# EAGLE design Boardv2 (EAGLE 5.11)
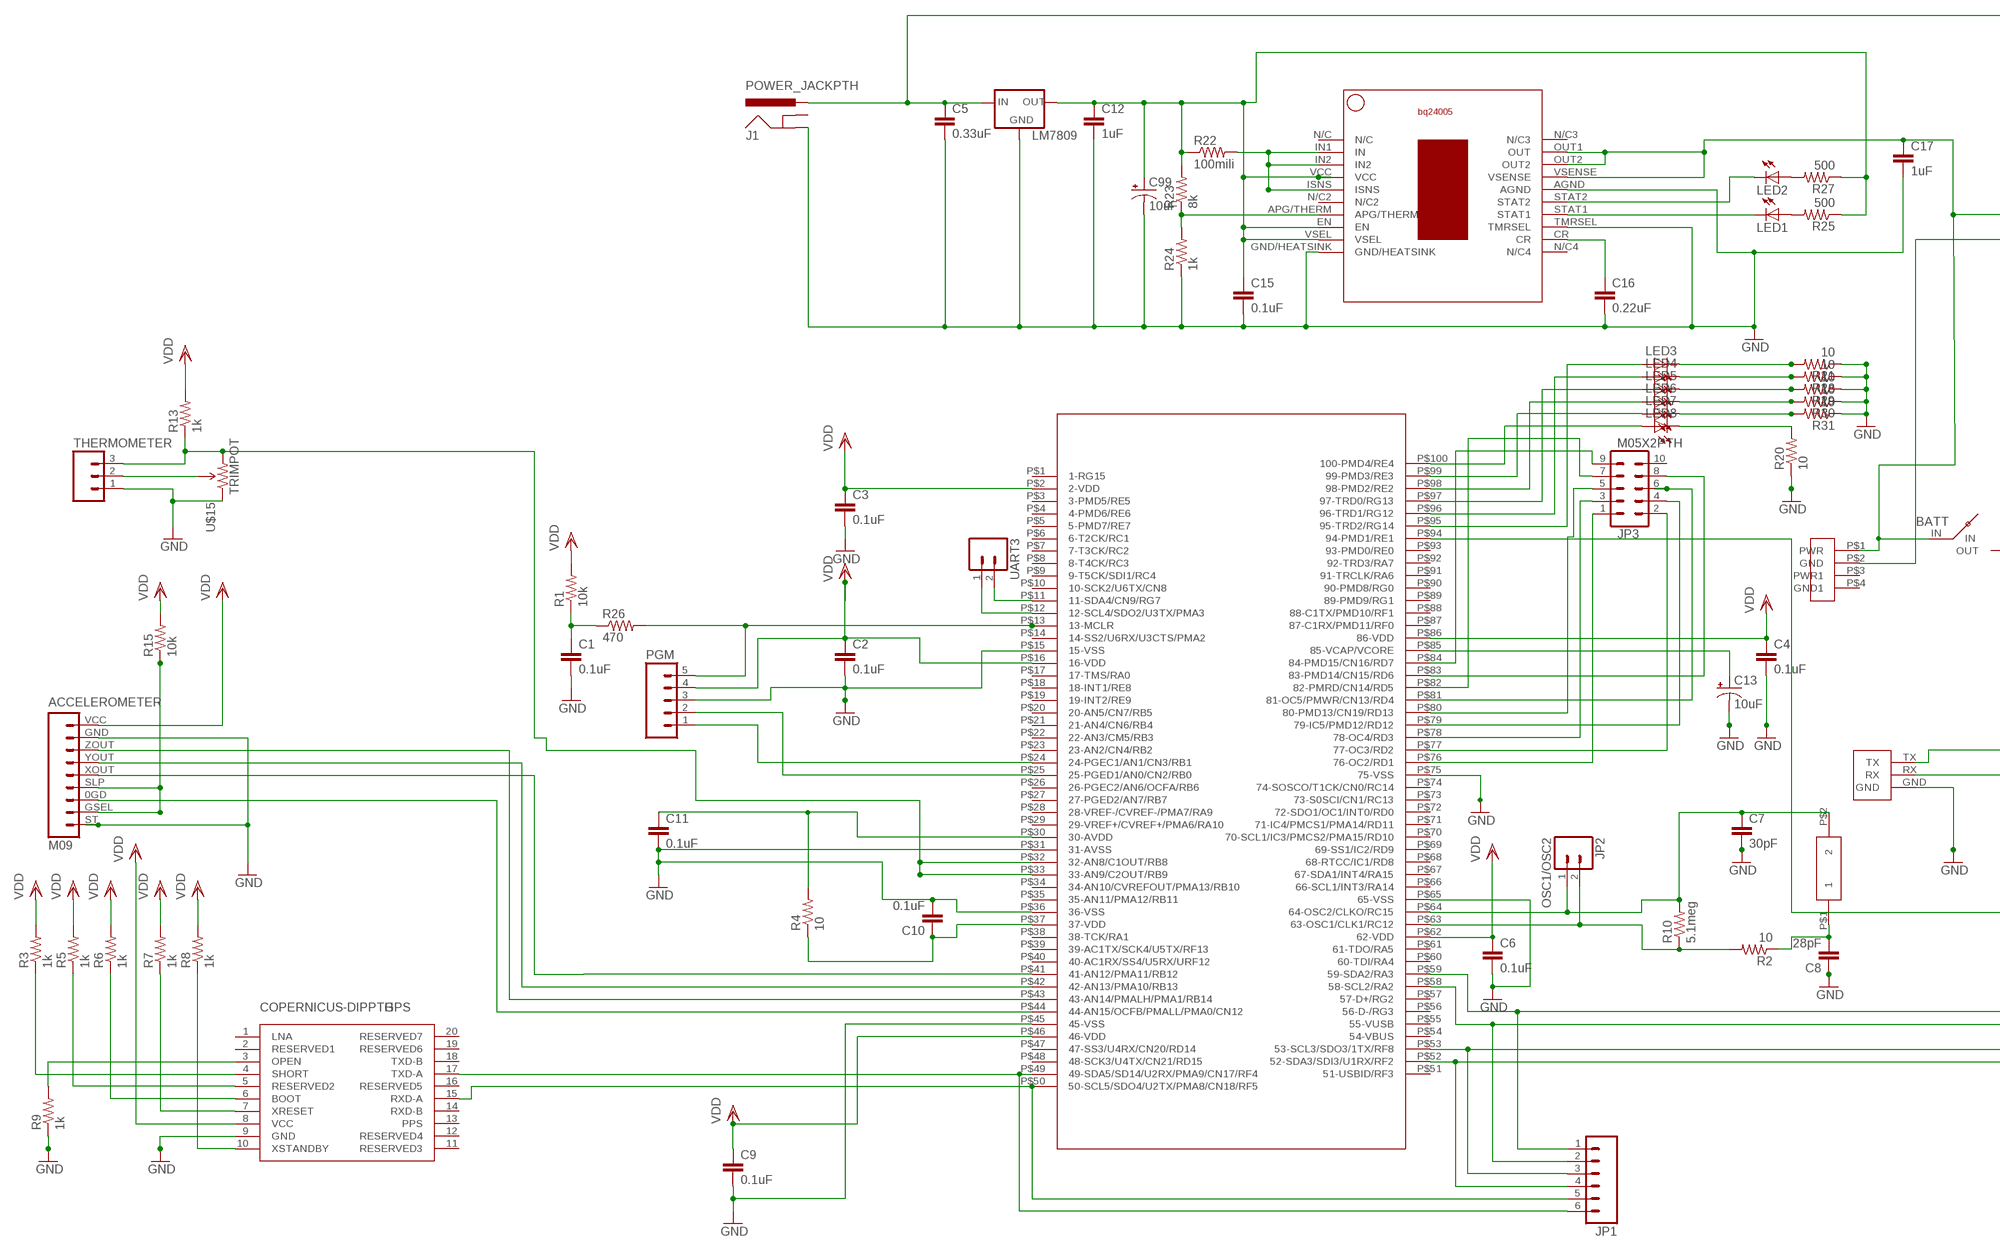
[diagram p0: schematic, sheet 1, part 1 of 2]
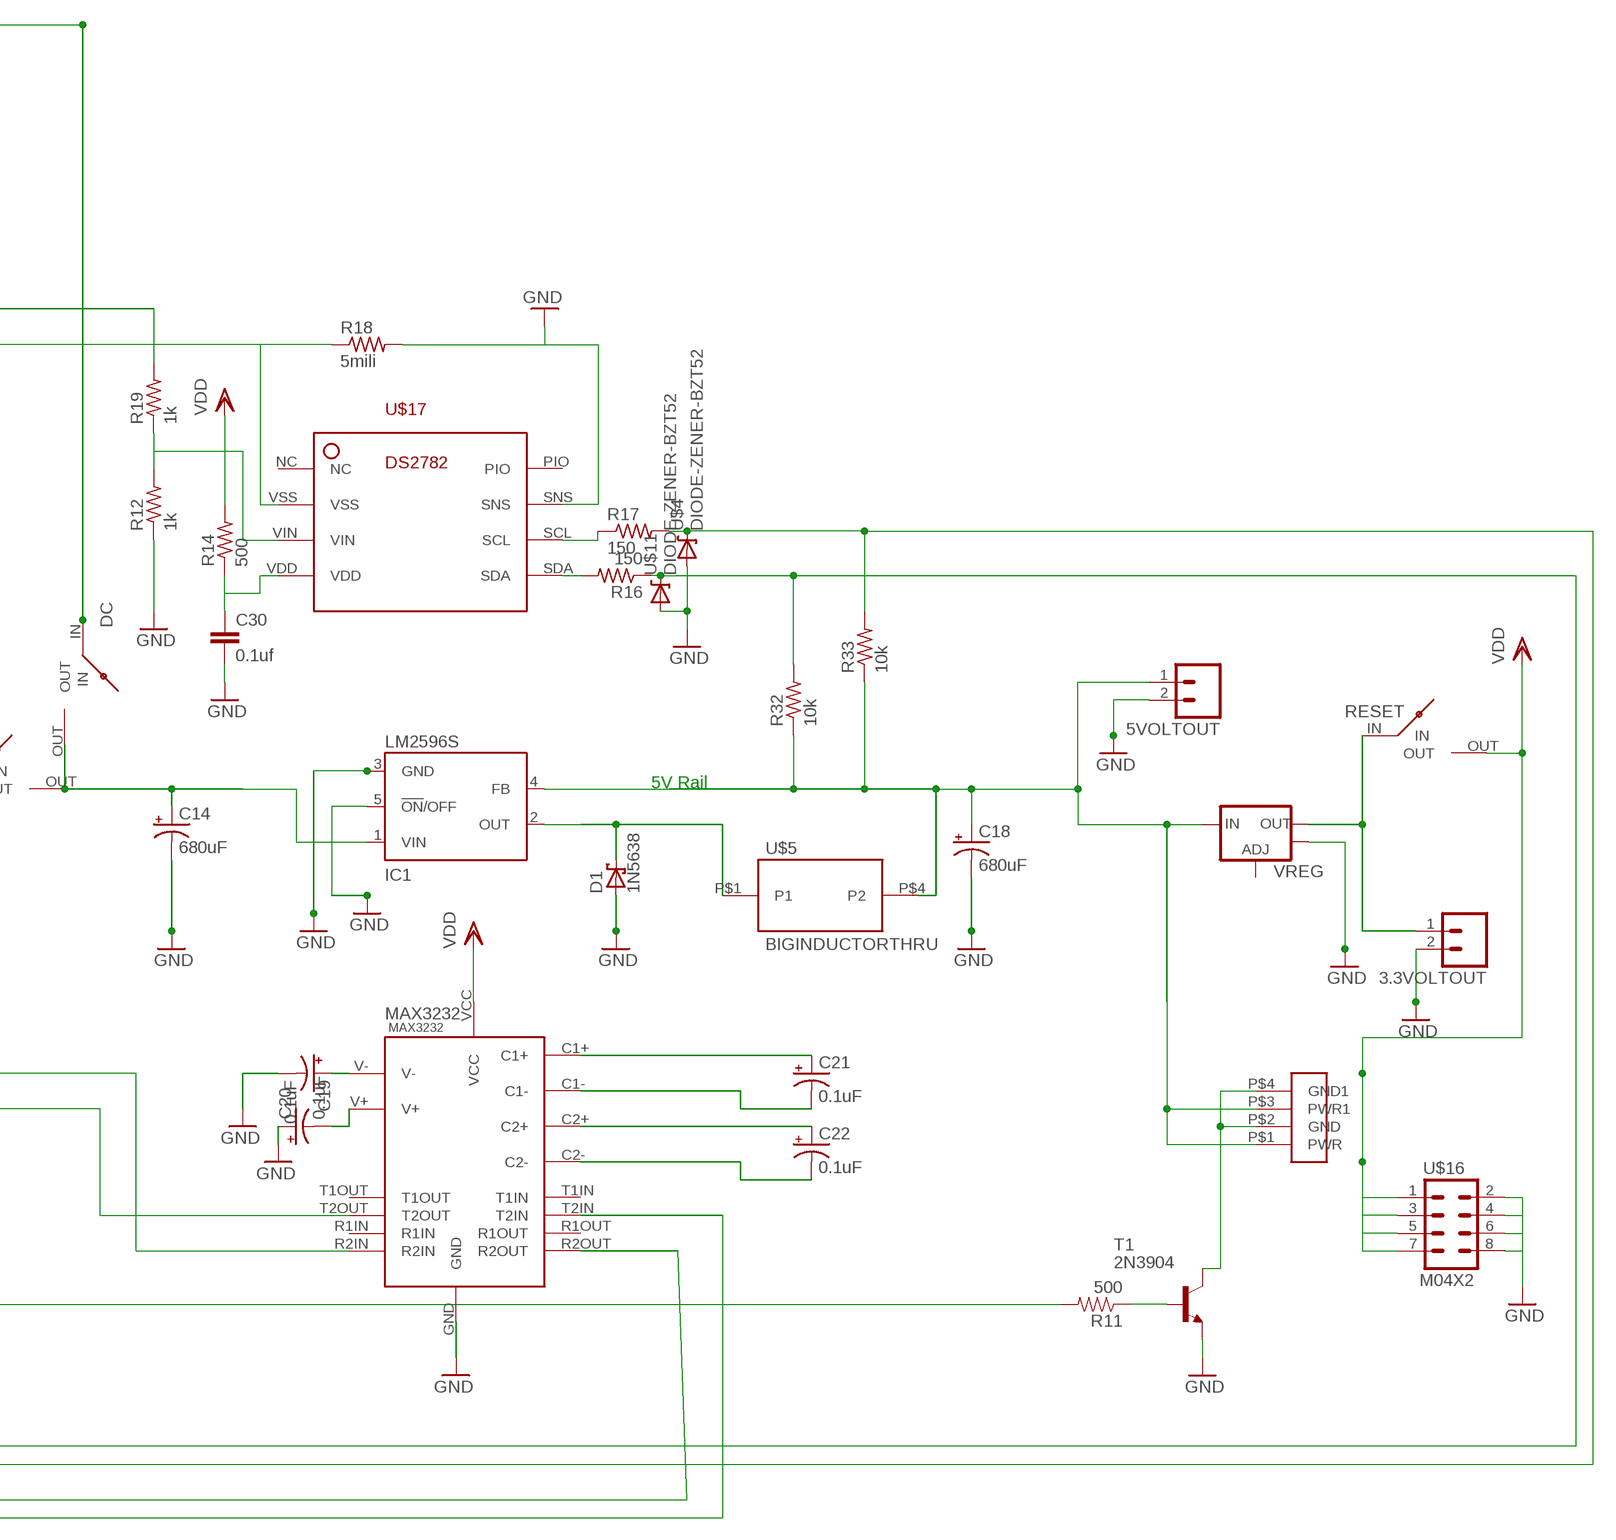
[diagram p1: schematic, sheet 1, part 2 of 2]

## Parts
3.3VOLTOUT  M02LOCK  [1X02_LOCK]
5VOLTOUT  M02PTH  [1X02]
ACCELEROMETER  M09  [1X09]
BATT  HUD_LOAD_SWITCH  [1X02@1]
C1  0.1uF  CAP1206  [1206]
C2  0.1uF  CAP1206  [1206]
C3  0.1uF  CAP1206  [1206]
C4  0.1uF  CAP1206  [1206]
C5  0.33uF  CAP1206  [1206]
C6  0.1uF  CAP1206  [1206]
C7  30pF  CAP1206  [1206]
C8  28pF  CAP1206  [1206]
C9  0.1uF  CAP1206  [1206]
C10  0.1uF  CAP1206  [1206]
C11  0.1uF  CAP1206  [1206]
C12  1uF  CAP1206  [1206]
C13  10uF  CAP_POL1206-KIT  [EIA3216-KIT]
C14  680uF  CAP_POLG  [PANASONIC_G]
C15  0.1uF  CAP1206  [1206]
C16  0.22uF  CAP1206  [1206]
C17  1uF  CAP1206  [1206]
C18  680uF  CAP_POLG  [PANASONIC_G]
C19  0.1uF  CAP_POL  [HUD_4MM_CAP_POL]
C20  0.1uF  CAP_POL  [HUD_4MM_CAP_POL]
C21  0.1uF  CAP_POL  [HUD_4MM_CAP_POL]
C22  0.1uF  CAP_POL  [HUD_4MM_CAP_POL]
C30  0.1uf  CAP1206  [1206]
C99  10uF  CAP_POLC  [PANASONIC_C]
D1  1N5638  SCHOTTKY-DIODESMC  [SMC]
DC  HUD_LOAD_SWITCH  [1X02@1]
GPS  COPERNICUS-DIPPTH  [COPERNICUS-DIP]
IC1  LM2596S  [TO263-5]
J1  POWER_JACKPTH  [POWER_JACK_PTH]
JP1  M06SIP  [1X06]
JP2  OSC1/OSC2  M02NG  [1X02]
JP3  M05X2PTH  [AVR_ICSP]
LED1  LED1206  [LED-1206]
LED2  LED1206  [LED-1206]
LED3  LED1206  [LED-1206]
LED4  LED1206  [LED-1206]
LED5  LED1206  [LED-1206]
LED6  LED1206  [LED-1206]
LED7  LED1206  [LED-1206]
LED8  LED1206  [LED-1206]
LM7809  V_REG_78XX-TO-220  [TO-220-ALT]
MAX3232  MAX3232TSOP-16  [MAX3232]
OSC  OSCILLATOR  [OSCILLATOR]
PGM  M05LOCK  [1X05_LOCK]
R1  10k  R-US_M1206  [M1206]
R2  10  R-US_M1206  [M1206]
R3  1k  R-US_M1206  [M1206]
R4  10  R-US_M1206  [M1206]
R5  1k  R-US_M1206  [M1206]
R6  1k  R-US_M1206  [M1206]
R7  1k  R-US_M1206  [M1206]
R8  1k  R-US_M1206  [M1206]
R9  1k  R-US_M1206  [M1206]
R10  5.1meg  R-US_M1206  [M1206]
R11  500  RESISTOR1206  [1206]
R12  1k  R-US_M1206  [M1206]
R13  1k  R-US_M1206  [M1206]
R14  500  R-US_M1206  [M1206]
R15  10k  R-US_M1206  [M1206]
R16  150  R-US_M1206  [M1206]
R17  150  R-US_M1206  [M1206]
R18  5mili  R-US_M1206  [M1206]
R19  1k  R-US_M1206  [M1206]
R20  10  RESISTOR1206  [1206]
R21  10  RESISTOR1206  [1206]
R22  100mili  RESISTOR1206  [1206]
R23  8k  RESISTOR1206  [1206]
R24  1k  RESISTOR1206  [1206]
R25  500  RESISTOR1206  [1206]
R26  470  R-US_M1206  [M1206]
R27  500  RESISTOR1206  [1206]
R28  10  RESISTOR1206  [1206]
R29  10  RESISTOR1206  [1206]
R30  10  RESISTOR1206  [1206]
R31  10  RESISTOR1206  [1206]
R32  10k  R-US_M1206  [M1206]
R33  10k  R-US_M1206  [M1206]
RESET  HUD_LOAD_SWITCH  [1X02@1]
T1  2N3904  [TO92]
THERMOMETER  M03LOCK  [1X03_LOCK]
U$1  PIC32MX564F128L  [PIC32]
U$2  BQ24005TSSOP-20VAR  [BQ24005]
U$4  DIODE-ZENER-BZT52  [SOD-323]
U$5  BIGINDUCTORTHRU  [BIGINDUCTOR]
U$6  4PINCON  [4PINCON]
U$7  4PINCON  [4PINCON]
U$9  UART_HEADERTHRU  [UART_HEADER]
U$11  DIODE-ZENER-BZT52  [SOD-323]
U$15  TRIMPOT  [TRIMPOT]
U$16  M04X2  [2X4]
U$17  DS2782TSSOP-8  [DS2782]
UART3  M02PTH  [1X02]
VREG  V_REG_LM1117SOT223  [SOT223]

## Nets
GND: 3.3VOLTOUT.2 5VOLTOUT.2 ACCELEROMETER.GND ACCELEROMETER.ST C1.2 C2.2 C3.2 C4.2 C5.2 C6.2 C7.2 C8.1 C9.2 C10.2 C11.2 C12.2 C13.C(-) C14.- C15.2 C16.2 C17.2 C18.- C19.MINUS(-) C20.PLUS(+) C30.2 C99.- D1.A GPS.9(GND) IC1.3(GND) IC1.5(!ON!/OFF) J1.GND LM7809.GND MAX3232.GND PGM.3 R9.1 R12.1 R18.2 R20.1 R21.1 R24.1 R28.1 R29.1 R30.1 R31.1 T1.3(E) THERMOMETER.1 U$1.P$15(15-VSS) U$1.P$31(31-AVSS) U$1.P$36(36-VSS) U$1.P$45(45-VSS) U$1.P$65(65-VSS) U$1.P$75(75-VSS) U$2.AGND U$2.GND/HEATSINK U$2.TMRSEL U$4.2(A) U$9.GND U$11.2(A) U$15.P$1(CCW) U$16.2 U$16.4 U$16.6 U$16.8 U$17.SNS VREG.4(OUT)
N$1: C1.1 R1.1 R26.1
N$2: C7.1 JP2.1 OSC.P$2 R10.2 U$1.P$64(64-OSC2/CLKO/RC15)
N$3: R13.1 THERMOMETER.3 U$1.P$32(32-AN8/C1OUT/RB8) U$1.P$33(33-AN9/C2OUT/RB9) U$15.P$3(CW)
N$4: PGM.1 U$1.P$24(24-PGEC1/AN1/CN3/RB1)
N$5: PGM.2 U$1.P$25(25-PGED1/AN0/CN2/RB0)
N$6: BATT.OUT C14.+ DC.OUT IC1.1(VIN)
N$7: C8.2 OSC.P$1 R2.1
N$8: GPS.15(RXD-A) JP1.5 U$1.P$50(50-SCL5/SDO4/U2TX/PMA8/CN18/RF5)
N$9: LED7.C R31.2
N$10: C30.1 R14.1 U$17.VDD
N$11: ACCELEROMETER.GSEL ACCELEROMETER.SLP R15.1
N$12: R18.1 U$6.P$2(GND) U$17.VSS
N$13: GPS.3(OPEN) R9.2
N$14: JP3.9 U$1.P$84(84-PMD15/CN16/RD7)
N$15: LED8.A U$1.P$100(100-PMD4/RE4)
N$16: GPS.10(XSTANDBY) R8.1
N$17: GPS.7(XRESET) R7.1
N$18: GPS.6(BOOT) R6.1
N$19: GPS.5(RESERVED2) R5.1
N$20: C5.1 DC.IN J1.PWR LM7809.IN
N$21: LED7.A U$1.P$99(99-PMD3/RE3)
N$22: LED6.A U$1.P$98(98-PMD2/RE2)
N$23: LED5.A U$1.P$97(97-TRD0/RG13)
N$24: LED4.A U$1.P$96(96-TRD1/RG12)
N$25: R22.2 U$2.IN1(IN) U$2.IN2 U$2.ISNS
N$26: R23.1 R24.2 U$2.APG/THERM
N$27: ACCELEROMETER.0GD U$1.P$44(44-AN15/OCFB/PMALL/PMA0/CN12)
N$28: BATT.IN C17.1 R19.2 U$2.OUT1(OUT) U$2.OUT2 U$2.VSENSE U$6.P$1(PWR)
N$29: LED3.A U$1.P$95(95-TRD2/RG14)
N$30: C16.1 U$2.CR
N$31: LED2.A R27.2
N$32: LED1.A R25.2
N$33: JP3.1 U$1.P$76(76-OC2/RD1)
N$34: LED1.C U$2.STAT1
N$35: LED2.C U$2.STAT2
N$36: 5VOLTOUT.1 C18.+ IC1.4(FB) R32.1 R33.1 U$5.P$4(P2) U$7.P$1(PWR) U$7.P$3(PWR1) VREG.3(IN)
N$37: U$1.P$11(11-SDA4/CN9/RG7) UART3.2
N$38: C12.1 C15.1 C99.+ LM7809.OUT R22.1 R23.2 R25.1 R27.1 U$2.EN U$2.VCC U$2.VSEL
N$39: JP3.2 U$1.P$77(77-OC3/RD2)
N$40: JP3.3 U$1.P$78(78-OC4/RD3)
N$41: JP3.4 U$1.P$79(79-IC5/PMD12/RD12)
N$42: THERMOMETER.2 U$15.P$2(WIPER)
N$43: JP3.6 U$1.P$81(81-OC5/PMWR/CN13/RD4)
N$44: JP3.8 U$1.P$83(83-PMD14/CN15/RD6)
N$45: ACCELEROMETER.XOUT U$1.P$41(41-AN12/PMA11/RB12)
N$46: ACCELEROMETER.YOUT U$1.P$42(42-AN13/PMA10/RB13)
N$47: ACCELEROMETER.ZOUT U$1.P$43(43-AN14/PMALH/PMA1/RB14)
N$48: C10.1 R4.1 U$1.P$37(37-VDD)
N$49: JP3.5 U$1.P$80(80-PMD13/CN19/RD13)
N$50: JP3.7 U$1.P$82(82-PMRD/CN14/RD5)
N$51: C11.1 R4.2 U$1.P$30(30-AVDD)
N$52: U$1.P$12(12-SCL4/SDO2/U3TX/PMA3) UART3.1
N$53: LED3.C R21.2
N$54: LED4.C R28.2
N$55: LED5.C R29.2
N$56: LED6.C R30.2
N$57: JP2.2 R2.2 R10.1 U$1.P$63(63-OSC1/CLK1/RC12)
N$58: LED8.C R20.2
N$59: R11.2 U$1.P$94(94-PMD1/RE1)
N$60: PGM.5 R26.2 U$1.P$13(13-MCLR)
N$61: JP1.2 R17.2 R33.2 U$1.P$58(58-SCL2/RA2) U$4.1(C)
N$62: R17.1 U$17.SCL
N$63: MAX3232.T2OUT U$9.RX
N$64: R12.2 R19.1 U$17.VIN
N$65: R11.1 T1.2(B)
N$66: T1.1(C) U$7.P$2(GND) U$7.P$4(GND1)
N$67: GPS.4(SHORT) R3.1
N$68: 3.3VOLTOUT.1 RESET.IN VREG.2(OUT)
N$69: JP1.3 MAX3232.R2OUT U$1.P$53(53-SCL3/SDO3/1TX/RF8)
N$70: R16.2 U$17.SDA
N$73: C13.A(+) U$1.P$85(85-VCAP/VCORE)
N$92: GPS.17(TXD-A) JP1.6 U$1.P$49(49-SDA5/SD14/U2RX/PMA9/CN17/RF4)
N$96: D1.C IC1.2(OUT) U$5.P$1(P1)
N$97: JP1.1 R16.1 R32.2 U$1.P$59(59-SDA2/RA3) U$11.1(C)
N$116: JP1.4 MAX3232.T2IN U$1.P$52(52-SDA3/SDI3/U1RX/RF2)
N$117: C21.PLUS(+) MAX3232.C1+
N$118: C21.MINUS(-) MAX3232.C1-
N$119: C22.PLUS(+) MAX3232.C2+
N$120: C22.MINUS(-) MAX3232.C2-
N$121: C19.PLUS(+) MAX3232.V-
N$122: C20.MINUS(-) MAX3232.V+
N$123: MAX3232.R2IN U$9.TX
VDD: ACCELEROMETER.VCC C2.1 C3.1 C4.1 C6.1 C9.1 GPS.8(VCC) MAX3232.VCC PGM.4 R1.2 R3.2 R5.2 R6.2 R7.2 R8.2 R13.2 R14.2 R15.2 RESET.OUT U$1.P$2(2-VDD) U$1.P$16(16-VDD) U$1.P$46(46-VDD) U$1.P$62(62-VDD) U$1.P$86(86-VDD) U$16.1 U$16.3 U$16.5 U$16.7
Unconnected: GPS.1(LNA) GPS.2(RESERVED1) GPS.11(RESERVED3) GPS.12(RESERVED4) GPS.13(PPS) GPS.14(RXD-B) GPS.16(RESERVED5) GPS.18(TXD-B) GPS.19(RESERVED6) GPS.20(RESERVED7) J1.GNDBREAK JP3.10 MAX3232.R1IN MAX3232.R1OUT MAX3232.T1IN MAX3232.T1OUT U$1.P$1(1-RG15) U$1.P$3(3-PMD5/RE5) U$1.P$4(4-PMD6/RE6) U$1.P$5(5-PMD7/RE7) U$1.P$6(6-T2CK/RC1) U$1.P$7(7-T3CK/RC2) U$1.P$8(8-T4CK/RC3) U$1.P$9(9-T5CK/SDI1/RC4) U$1.P$10(10-SCK2/U6TX/CN8) U$1.P$14(14-SS2/U6RX/U3CTS/PMA2) U$1.P$17(17-TMS/RA0) U$1.P$18(18-INT1/RE8) U$1.P$19(19-INT2/RE9) U$1.P$20(20-AN5/CN7/RB5) U$1.P$21(21-AN4/CN6/RB4) U$1.P$22(22-AN3/CM5/RB3) U$1.P$23(23-AN2/CN4/RB2) U$1.P$26(26-PGEC2/AN6/OCFA/RB6) U$1.P$27(27-PGED2/AN7/RB7) U$1.P$28(28-VREF-/CVREF-/PMA7/RA9) U$1.P$29(29-VREF+/CVREF+/PMA6/RA10) U$1.P$34(34-AN10/CVREFOUT/PMA13/RB10) U$1.P$35(35-AN11/PMA12/RB11) U$1.P$38(38-TCK/RA1) U$1.P$39(39-AC1TX/SCK4/U5TX/RF13) U$1.P$40(40-AC1RX/SS4/U5RX/URF12) U$1.P$47(47-SS3/U4RX/CN20/RD14) U$1.P$48(48-SCK3/U4TX/CN21/RD15) U$1.P$51(51-USBID/RF3) U$1.P$54(54-VBUS) U$1.P$55(55-VUSB) U$1.P$56(56-D-/RG3) U$1.P$57(57-D+/RG2) U$1.P$60(60-TDI/RA4) U$1.P$61(61-TDO/RA5) U$1.P$66(66-SCL1/INT3/RA14) U$1.P$67(67-SDA1/INT4/RA15) U$1.P$68(68-RTCC/IC1/RD8) U$1.P$69(69-SS1/IC2/RD9) U$1.P$70(70-SCL1/IC3/PMCS2/PMA15/RD10) U$1.P$71(71-IC4/PMCS1/PMA14/RD11) U$1.P$72(72-SDO1/OC1/INT0/RD0) U$1.P$73(73-S0SCI/CN1/RC13) U$1.P$74(74-SOSCO/T1CK/CN0/RC14) U$1.P$87(87-C1RX/PMD11/RF0) U$1.P$88(88-C1TX/PMD10/RF1) U$1.P$89(89-PMD9/RG1) U$1.P$90(90-PMD8/RG0) U$1.P$91(91-TRCLK/RA6) U$1.P$92(92-TRD3/RA7) U$1.P$93(93-PMD0/RE0) U$2.N/C U$2.N/C2 U$2.N/C3 U$2.N/C4 U$6.P$3(PWR1) U$6.P$4(GND1) U$17.NC U$17.PIO VREG.1(ADJ)

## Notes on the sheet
- 5V Rail

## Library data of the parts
3.3VOLTOUT 5VOLTOUT UART3 = SparkFun:M02: Header 2
ACCELEROMETER = SparkFun:M09: Header 9 Standard 9-pin 0.1" header. Use with straight break away headers (SKU : PRT-00116), right angle break away headers (PRT-00553), swiss pins (PRT-00743), machine pins (PRT-00117), and female headers (PRT-00115).
BATT DC RESET = SparkFun:HUD_LOAD_SWITCH
C1-C12 C15-C17 C30 = SparkFun:CAP: Capacitor
C13 C14 C18-C22 C99 = SparkFun:CAP_POL: Capacitor Polarized
D1 = diode:SCHOTTKY-DIODE: Schottky Diode
GPS = SparkFun:COPERNICUS-DIP
IC1 = national-semiconductor:LM2596: SIMPLE SWITCHER® Power Converter 150 kHz 3A Step-Down Voltage Regulator Source: http://www.national.com/ds/LM/LM2596.pdf; MF: NATIONAL SEMICONDUCTOR; MPN: LM2596S-ADJ/NOPB; OC_FARNELL: 9494367; OC_NEWARK: 41K3842
J1 = SparkFun:POWER_JACK: Power Jack This is the standard 5.5mm barrel jack for power. The PTH is the most common, proven, reliable, footprint. All others are experimental. The Slot footprint only works if the mill layer is transmitted to the PCB fab house so be warned. Spark Fun Electronics SKU : PRT-00119. Mating wall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
JP1 = SparkFun:M06: Header 6 Standard 6-pin 0.1" header. Use with straight break away headers (SKU : PRT-00116), right angle break away headers (PRT-00553), swiss pins (PRT-00743), machine pins (PRT-00117), and female headers (PRT-00115). Molex polarized connector foot print use with SKU : PRT-08094 with associated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
JP2 = SparkFun:M02NG
JP3 = SparkFun:M05X2: Header 5x2 Standard 10-pin dual row 0.1" header. Commonly used with AVR-ISP. Use with Spark Fun Electronics SKU: PRT-00778
LED1-LED8 = SparkFun:LED: LEDs
LM7809 = SparkFun:V_REG_78XX: Voltage Regulator Standard 7805 5V regulator. IGO (Input Ground Output). Spark Fun Electronics SKU : COM-00107
MAX3232 = SMD Mods:MAX3232
OSC = IncredibleHud:OSCILLATOR
PGM = SparkFun:M05: Header 5 Standard 5-pin 0.1" header. Use with straight break away headers (SKU : PRT-00116), right angle break away headers (PRT-00553), swiss pins (PRT-00743), machine pins (PRT-00117), and female headers (PRT-00115). Molex polarized connector foot print use with SKU : PRT-08230 with associated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
R1-R10 R12-R19 R26 R32 R33 = resistor:R-US_: RESISTOR, American symbol
R11 R20-R25 R27-R31 = SparkFun:RESISTOR: Resistor
T1 = transistor:2N3904: NPN TRANSISTOR
THERMOMETER = SparkFun:M03: Header 3 Standard 3-pin 0.1" header. Use with straight break away headers (SKU : PRT-00116), right angle break away headers (PRT-00553), swiss pins (PRT-00743), machine pins (PRT-00117), and female headers (PRT-00115). Molex polarized connector foot print use with SKU : PRT-08232 with associated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
U$1 = IncredibleHud:PIC32MX564F128L
U$2 = SMD Mods:BQ24005
U$4 U$11 = SparkFun:DIODE-ZENER: Zener Diode
U$5 = SMD Mods:BIGINDUCTOR
U$6 U$7 = IncredibleHud:4PINCON
U$9 = SparkFun:UART_HEADER
U$15 = SMD Mods:TRIMPOT
U$16 = SparkFun:M04X2
U$17 = SMD Mods:DS2782
VREG = SparkFun:V_REG_LM1117: Voltage Regulator LM1117 Standard adjustable voltage regulator but in SMD form. Spark Fun Electronics SKU : COM-00595

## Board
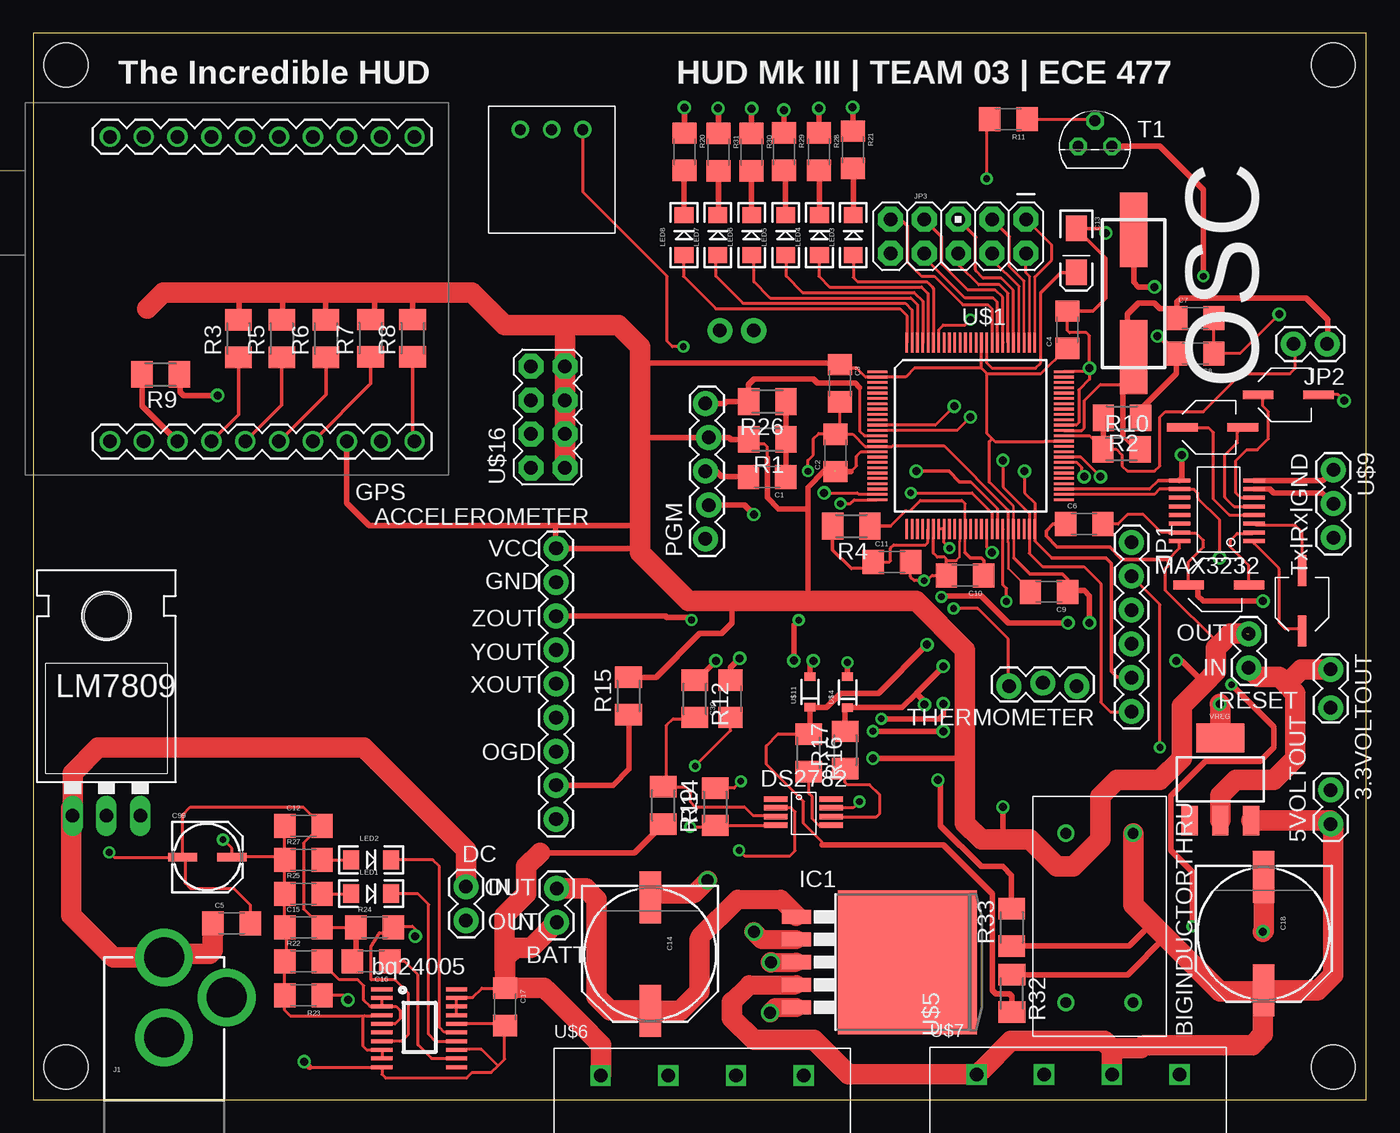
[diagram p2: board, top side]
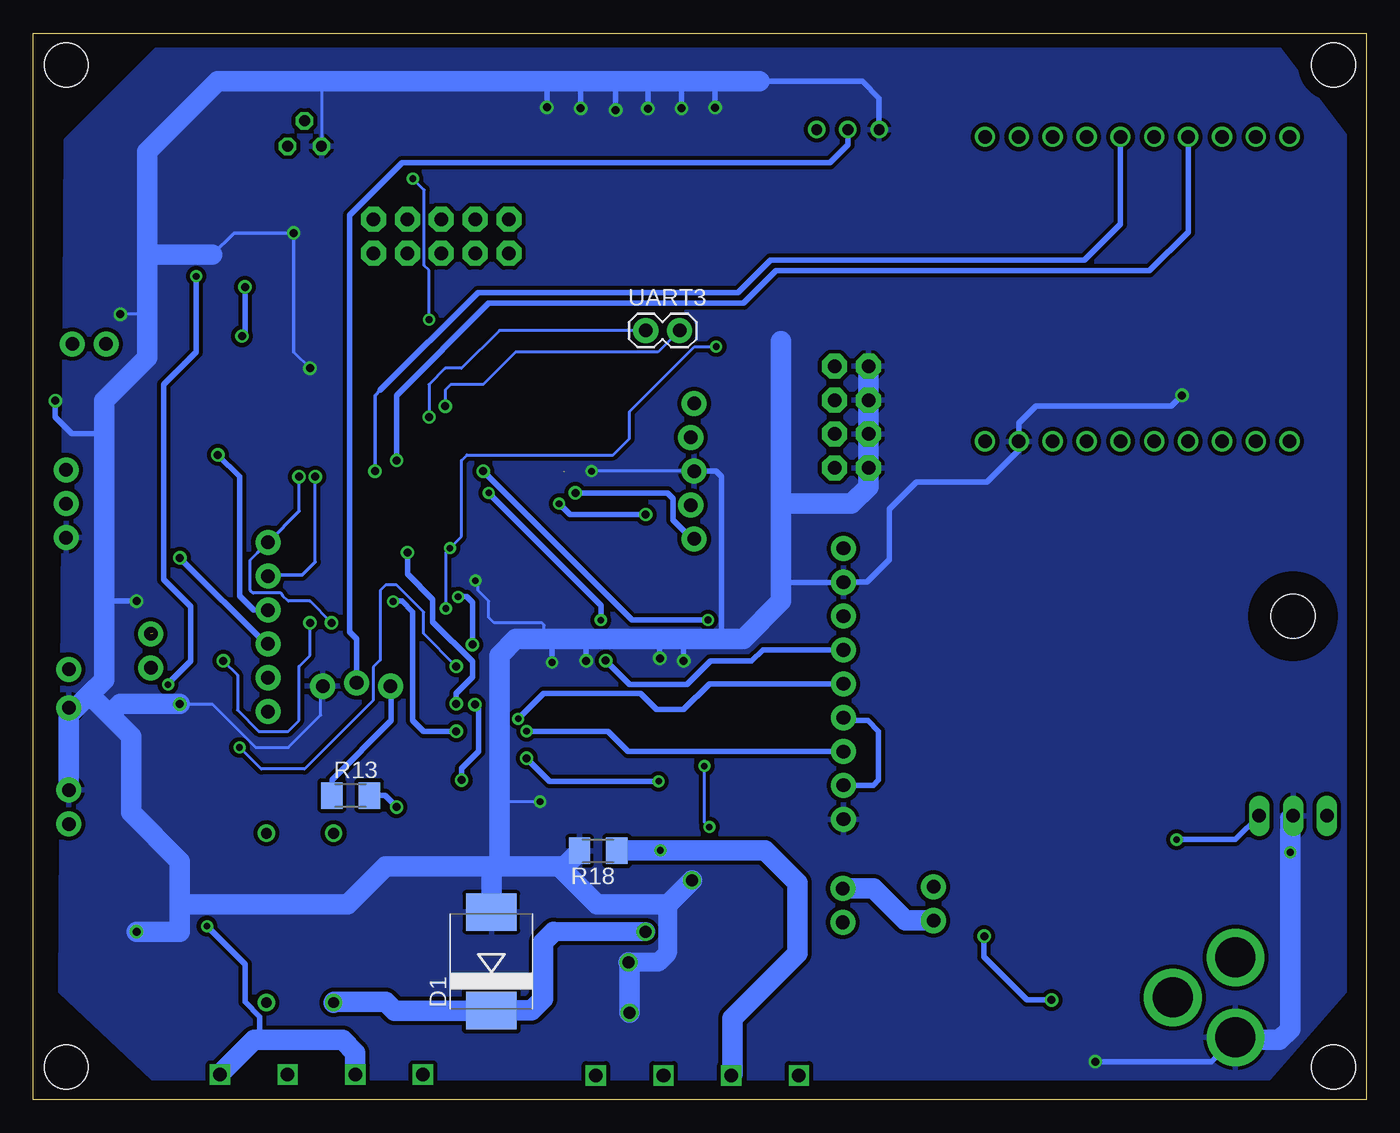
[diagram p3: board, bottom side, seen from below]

Size 100 x 80 mm. Coordinates in mm from the lower left corner, seen from the top.
Outline: 0,0 100,0 100,80 0,80 0,0
Copper layers (1*16): Top 0.035mm / dielectric 1.5mm / Bottom 0.035mm
Design rules "default *": minimum track width 7mil, minimum drill 16mil, track to track 6mil, track to pad 6mil, pad to pad 6mil, via to via 7mil, smd to smd 6mil, copper to edge 40mil, drill to drill 8mil, minimum pad ring 10mil, minimum via ring 8mil, stop-mask expansion 4mil, vias tented up to drill 0mil, thermal gap 10mil

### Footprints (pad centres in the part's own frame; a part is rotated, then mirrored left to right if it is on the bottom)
1X02_LOCK = drill 1.016 pad 1.88 round: 1 -0.178,0; 2 2.718,0
1X02 = drill 1.016 pad 1.88 round: 1 0,0; 2 2.54,0
1X09 = drill 1.016 pad 1.88 round: 0GD 0,-5.08; GND 0,7.62; GSEL 0,-7.62; SLP 0,-2.54; ST 0,-10.16; VCC 0,10.16; XOUT 0,0; YOUT 0,2.54; ZOUT 0,5.08
1X02@1 = drill 1.016 pad 1.88 round: IN 0,1.54; OUT 0,-1
1206 = smd 1.6 x 1.8: 1 -1.4,0; 2 1.4,0
EIA3216-KIT = smd 1.9 x 1.6: A 1.65,0; C -1.65,0
PANASONIC_G = smd 3.9 x 1.6: + 4.25,0; - -4.25,0
HUD_4MM_CAP_POL = smd 2.3 x 0.65: MINUS 4.537,0; PLUS 0,0
PANASONIC_C = smd 2.2 x 0.65: + 1.9,-0.2; - -1.8,-0.2
SMC = smd 2.8 x 3.8: A 3.7,0; C -3.7,0
COPERNICUS-DIP = drill 1.016 round: 1 0,0; 2 2.54,0; 3 5.08,0; 4 7.62,0; 5 10.16,0; 6 12.7,0; 7 15.24,0; 8 17.78,0; 9 20.32,0; 10 22.86,0; 11 22.86,22.86; 12 20.32,22.86; 13 17.78,22.86; 14 15.24,22.86; 15 12.7,22.86; 16 10.16,22.86; 17 7.62,22.86; 18 5.08,22.86; 19 2.54,22.86; 20 0,22.86
TO263-5 = smd 1.067 x 2.159: 1 -3.404,-5.791; 2 -1.702,-5.791; 3 0,-5.791; 4 1.702,-5.791; 5 3.404,-5.791 | smd 10.8 x 10.41: 6 0,2.54
POWER_JACK_PTH = drill 2.997 pad 4.318 round: GND 0,7.7; GNDBREAK 4.7,10.7; PWR 0,13.7
1X06 = drill 1.016 pad 1.88 round: 1 0,0; 2 2.54,0; 3 5.08,0; 4 7.62,0; 5 10.16,0; 6 12.7,0
AVR_ICSP = drill 1.016 pad 1.88 octagon: 1 -1.27,5.08; 2 1.27,5.08; 3 -1.27,2.54; 4 1.27,2.54; 5 -1.27,0; 6 1.27,0; 7 -1.27,-2.54; 8 1.27,-2.54; 9 -1.27,-5.08; 10 1.27,-5.08
LED-1206 = smd 1.2 x 1.4: A -1.5,0; C 1.5,0
TO-220-ALT = drill 1.016 long: GND 0,-3.81; IN -2.54,-3.81; OUT 2.54,-3.81 | hole 3.302: 0,11.176
MAX3232 = smd 0.3 x 1.6: C1+ -1.73,-3; C1- -0.43,-3; C2+ 0.22,-3; C2- 0.87,-3; GND -1.08,2.6; R1IN 0.22,2.6; R1OUT 0.87,2.6; R2IN 2.82,-3; R2OUT 2.82,2.6; T1IN 1.52,2.6; T1OUT -0.43,2.6; T2IN 2.17,2.6; T2OUT 2.17,-3; V+ -1.08,-3; V- 1.52,-3; VCC -1.73,2.6
OSCILLATOR = smd 5.563 x 2.057: P$1 0,0; P$2 9.55,0
1X05_LOCK = drill 1.016 pad 1.88 round: 1 0,0.127; 2 2.54,-0.127; 3 5.08,0.127; 4 7.62,-0.127; 5 10.16,0.127
M1206 = smd 1.6 x 2: 1 -1.4,0; 2 1.4,0
TO92 = drill 0.813 octagon: 1 1.27,0; 2 0,1.905; 3 -1.27,0
1X03_LOCK = drill 1.016 pad 1.88 round: 1 0,0.127; 2 2.54,-0.127; 3 5.08,0.127
PIC32 = smd 1.5 x 0.2: P$1 -7,4.8; P$2 -7,4.4; P$3 -7,4; P$4 -7,3.6; P$5 -7,3.2; P$6 -7,2.8; P$7 -7,2.4; P$8 -7,2; P$9 -7,1.6; P$10 -7,1.2; P$11 -7,0.8; P$12 -7,0.4; P$13 -7,0; P$14 -7,-0.4; P$15 -7,-0.8; P$16 -7,-1.2; P$17 -7,-1.6; P$18 -7,-2; P$19 -7,-2.4; P$20 -7,-2.8; P$21 -7,-3.2; P$22 -7,-3.6; P$23 -7,-4; P$24 -7,-4.4; P$25 -7,-4.8; P$51 7,-4.8; P$52 7,-4.4; P$53 7,-4; P$54 7,-3.6; P$55 7,-3.2; P$56 7,-2.8; P$57 7,-2.4; P$58 7,-2; P$59 7,-1.6; P$60 7,-1.2; P$61 7,-0.8; P$62 7,-0.4; P$63 7,0; P$64 7,0.4; P$65 7,0.8; P$66 7,1.2; P$67 7,1.6; P$68 7,2; P$69 7,2.4; P$70 7,2.8; P$71 7,3.2; P$72 7,3.6; P$73 7,4; P$74 7,4.4; P$75 7,4.8 | smd 0.2 x 1.5: P$26 -4.8,-7; P$27 -4.4,-7; P$28 -4,-7; P$29 -3.6,-7; P$30 -3.2,-7; P$31 -2.8,-7; P$32 -2.4,-7; P$33 -2,-7; P$34 -1.6,-7; P$35 -1.2,-7; P$36 -0.8,-7; P$37 -0.4,-7; P$38 0,-7; P$39 0.4,-7; P$40 0.8,-7; P$41 1.2,-7; P$42 1.6,-7; P$43 2,-7; P$44 2.4,-7; P$45 2.8,-7; P$46 3.2,-7; P$47 3.6,-7; P$48 4,-7; P$49 4.4,-7; P$50 4.8,-7; P$76 4.8,7; P$77 4.4,7; P$78 4,7; P$79 3.6,7; P$80 3.2,7; P$81 2.8,7; P$82 2.4,7; P$83 2,7; P$84 1.6,7; P$85 1.2,7; P$86 0.8,7; P$87 0.4,7; P$88 0,7; P$89 -0.4,7; P$90 -0.8,7; P$91 -1.2,7; P$92 -1.6,7; P$93 -2,7; P$94 -2.4,7; P$95 -2.8,7; P$96 -3.2,7; P$97 -3.6,7; P$98 -4,7; P$99 -4.4,7; P$100 -4.8,7
BQ24005 = smd 0.3 x 1.6: AGND -0.4,2.6; APG/THERM 0.9,-3; CR 2.2,2.6; EN 1.55,-3; GND/HEATSINK 2.85,-3; IN1 -2.35,-3; IN2 -1.7,-3; ISNS -0.4,-3; N/C -3,-3; N/C2 0.25,-3; N/C3 -3,2.6; N/C4 2.85,2.6; OUT1 -2.35,2.6; OUT2 -1.7,2.6; STAT1 0.9,2.6; STAT2 0.25,2.6; TMRSEL 1.55,2.6; VCC -1.05,-3; VSEL 2.2,-3; VSENSE -1.05,2.6
SOD-323 = smd 0.63 x 0.83: 1 -1.15,0; 2 1.15,0
BIGINDUCTOR = drill 0.8 round: P$1 2.54,7.531; P$2 15.24,7.531; P$3 2.54,2.477; P$4 15.24,2.477
4PINCON = drill 1.016 square: P$1 3.505,9.906; P$2 8.585,9.906; P$3 13.665,9.906; P$4 18.745,9.906
UART_HEADER = drill 1.016 pad 1.88 round: GND 2.54,0; RX 0,0; TX -2.54,0
STAND-OFF = hole 3.302: 0,0
TRIMPOT = drill 0.8 round: P$1 2.4,7.75; P$2 4.75,7.75; P$3 7.099,7.75
2X4 = drill 1.016 pad 1.88 octagon: 1 -3.81,-1.27; 2 -3.81,1.27; 3 -1.27,-1.27; 4 -1.27,1.27; 5 1.27,-1.27; 6 1.27,1.27; 7 3.81,-1.27; 8 3.81,1.27
DS2782 = smd 0.42 x 1.78: NC -1,-2; PIO -1,2.16; SCL 0.3,2.16; SDA 0.95,2.16; SNS -0.35,2.16; VDD 0.95,-2; VIN 0.3,-2; VSS -0.35,-2
SOT223 = smd 1.219 x 2.235: 1 -2.311,-3.099; 2 0,-3.099; 3 2.311,-3.099 | smd 3.6 x 2.2: 4 0,3.099

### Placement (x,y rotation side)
3.3VOLTOUT  97.33,32.11 270 top
5VOLTOUT  97.33,20.68 90 top
ACCELEROMETER  39.22,31.19 0 top
BATT  39.27,14.83 180 top
C1  55.06,46.7 180 top
C2  60.2,48.51 90 top
C3  60.5,53.75 270 top
C4  77.57,57.76 90 top
C5  14.88,13.21 0 top
C6  78.84,43.18 0 top
C7  87.17,58.62 0 top
C8  87.17,55.98 180 top
C9  76.2,38.1 180 top
C10  69.9,39.32 180 top
C11  64.41,40.34 0 top
C12  20.27,20.52 0 top
C13  78.26,63.7 270 top
C14  46.28,10.92 270 top
C15  20.27,12.9 0 top
C16  25.35,10.36 180 top
C17  35.41,6.96 270 top
C18  92.3,12.45 270 top
C19  91.9,52.88 0 top
C20  86.66,38.61 0 top
C21  95.2,35.15 90 top
C22  86.21,50.44 0 top
C30  52.32,30.07 90 top
C99  13,18.39 0 top
D1  65.63,10.36 90 bottom
DC  32.46,14.43 0 top
GPS  5.74,49.38 0 top
IC1  63.04,10.31 270 top
J1  9.8,-3.05 0 top
JP1  82.4,41.81 270 top
JP2  97.08,56.69 180 top
JP3  69.39,64.77 270 top
LED1  25.35,15.44 0 top
LED2  25.35,17.98 0 top
LED3  61.52,64.87 90 top
LED4  58.98,64.87 90 top
LED5  56.44,64.87 90 top
LED6  53.9,64.87 90 top
LED7  51.36,64.87 90 top
LED8  48.82,64.87 90 top
LM7809  5.49,25.1 0 top
MAX3232  88.6,43.64 90 top
OSC  82.55,65.25 270 top
PGM  50.55,42.06 90 top
R1  55.07,49.53 180 top
R2  81.69,51.16 180 top
R3  15.39,57.1 90 top
R4  61.37,43.03 180 top
R5  18.64,57.1 90 top
R6  21.96,57.1 90 top
R7  25.31,57.12 90 top
R8  28.46,57.12 90 top
R9  9.55,54.41 180 top
R10  81.65,48.8 0 top
R11  73.15,73.56 180 top
R12  49.63,30.07 270 top
R13  76.2,22.81 0 bottom
R14  51.15,21.97 90 top
R15  44.65,30.28 90 top
R16  58.17,26.01 270 top
R17  60.91,26.21 90 top
R18  57.62,18.66 180 bottom
R19  47.27,22.07 270 top
R20  48.86,71.11 270 top
R21  61.49,71.26 270 top
R22  20.27,10.36 0 top
R23  20.27,7.82 180 top
R24  25.6,12.9 0 top
R25  20.27,15.44 0 top
R26  55.07,52.37 180 top
R27  20.27,17.98 0 top
R28  58.93,71.12 270 top
R29  56.31,71.12 270 top
R30  53.89,71.08 270 top
R31  51.39,71.08 270 top
R32  73.42,7.97 270 top
R33  73.4,12.92 90 top
RESET  91.19,33.93 180 top
T1  79.65,71.53 0 top
THERMOMETER  78.28,31.14 180 top
U$1  70.33,49.8 0 top
U$2  29.16,5.28 270 top
U$4  61.09,30.56 90 top
U$5  85,4.73 90 top
U$6  39.06,-8.1 0 top
U$7  67.26,-8.03 0 top
U$9  97.54,44.7 270 top
U$10  [STAND-OFF]  2.44,77.62 0 top
U$11  58.27,30.58 90 top
U$12  [STAND-OFF]  97.54,77.62 0 top
U$13  [STAND-OFF]  97.54,2.44 0 top
U$14  [STAND-OFF]  2.44,2.44 0 top
U$15  34.14,65.02 0 top
U$16  38.61,51.21 90 top
U$17  57.71,21.54 270 top
UART3  54.05,57.71 0 bottom
VREG  89.05,24.03 0 top

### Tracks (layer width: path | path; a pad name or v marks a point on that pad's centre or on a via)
GND  (via drill 0.5, 0.6, 0.9)
  Top 0.203: 69.23,40.44 69.49,40.7 69.49,41.86 69.52,41.88 69.52,42.79 U$1.P$36 | C9.2 74.8,38.18 73.15,39.83 73.15,41.82 73.13,41.84 U$1.P$45
  Top 0.229: C20.PLUS 86.67,40.34 87.78,41.45 87.78,41.96 87.27,42.47 86.08,42.47 MAX3232.GND 85.99,42.55 84.63,42.55 83.29,43.89 82.09,43.89 81.38,43.18 C6.2 | 78.99,54.6 U$1.P$75 | U$1.P$65 78.25,50.6 78.44,50.78 78.44,53.24 79.25,54.05 v79.25,54.86 79.25,57.3 79.03,57.53 77.74,57.53 77.57,57.7 77.57,58.57 | R24.1 C15.2 20.27,14.3 20.27,19.25 21.54,20.52 | U$2.TMRSEL 31.73,3.76 33.63,3.76 34.86,2.53 | C12.2 20.25,21.95 11.79,21.95 11.21,21.36 C99.- 11.18,18.16 6.07,18.16 v5.69,18.54 | 11.38,18.02 11.38,16.26 11.79,15.85 15.04,15.85 16.28,14.6 C5.2 | 34.86,2.53 34.36,2.03 32.92,2.03 32.51,1.63 26.42,1.63 26.16,1.88 U$2.GND/HEATSINK 20.73,2.43 | 34.86,2.53 35.36,3.03 35.36,5.51 | 35.28,5.68 U$2.AGND | 60.5,50.22 C3.2 | 60.5,50.22 C2.2 60.21,49.93 61.49,49.93 62.41,49 U$1.P$15 63.34,49.01 64.44,49.01 64.47,49.05 68.32,49.05 73.13,44.24 U$1.P$45 | 60.5,50.22 60.5,50.04 60.55,49.99 58.93,49.99 58.52,49.58 58.52,48.36 58.12,47.95 v58.12,47.14 | 68.5,40.38 C10.2 67.42,39.32 67.04,38.93 v66.83,38.93 66.1,38.93 65.81,39.22 C11.2 | 68.5,40.38 68.5,40.56 68.36,40.7 67.83,40.7 67.52,41.01 67.52,41.79 67.53,41.79 U$1.P$31 | 69.23,40.44 68.56,40.44 68.5,40.38 | C7.2 C8.1 90.53,55.98 v93.47,58.93 | C19.MINUS 97.89,52.88 v98.35,52.43 | U$17.SNS 61.51,21.89 v61.98,22.35
  Top 0.254: v80.47,65.02 80.14,65.35 C13.C 80.47,63.14 80.47,60.15 79.48,59.16 C4.2 77.57,58.57 | v79.25,54.86 78.99,54.6
  Top 0.406: 52.61,31.47 C30.2 52.32,32.43 v52.99,33.1 53.22,33.33 | 49.63,31.75 R12.1 49.76,31.47 v51.21,32.92 | C20.PLUS 87.38,38.61 87.38,37.8 87.78,37.39 v92.25,37.39 | U$11.2 58.27,32.66 v58.52,32.92 | v48.85,74.43 v48.86,74.42 R20.1 | R21.1 61.49,74.43 v61.47,74.45 | R31.1 51.39,74.35 v51.37,74.37 | v53.89,74.35 R30.1 | v56.31,74.25 R29.1 | v58.93,74.37 R28.1 | v13.82,52.83 11.28,52.83 11.01,53.1 11.01,54.34 R9.1 | U$4.2 61.09,32.79 v61.08,32.8 | R24.1 24.2,10.62 C16.2 | C12.2 21.54,20.52 | C99.- 11.38,18.02 | 35.36,5.51 C17.2 35.28,5.68 | v20.32,2.85 20.73,2.43 | PGM.3 51.21,47.14 51.61,46.74 53.62,46.74 C1.2
  Top 1.422: 55.36,10.31 IC1.3 | IC1.5 55.68,6.91 v55.27,6.5 | 46.55,15.44 49.58,15.44 v50.6,16.46
  Top 1.524: C14.- 46.55,15.44 | VREG.4 89.05,29.62 v89,29.67 | C18.- 92.3,12.65 v92.25,12.6 | v55.35,10.3 55.36,10.31
  Bottom 0.229: 80.47,56.08 v79.25,54.86 | 62.59,17.48 62.18,17.88 | 61.77,34.54 61.67,34.65 61.67,35.6 61.83,35.76 65.43,35.76 65.84,36.17 65.84,37.39 66.65,38.2 66.65,38.75 v66.83,38.93 | 92.66,26.82 92.35,27.13 | 94.08,28.65 93.07,29.67 v89,29.67 86.56,29.67 83.31,26.42 80.87,26.42 78.44,28.85 78.44,30.86 THERMOMETER.1 | 91.44,58.93 v93.47,58.93 | T1.3 78.38,76.35 78.44,76.4 | PGM.3 v58.12,47.14 | v61.98,22.35 64.26,22.35 65.02,21.59
  Bottom 0.254: 80.47,56.08 v80.47,65.02 84.94,65.02 86.56,63.4
  Bottom 0.406: 65.02,27.23 65.43,27.64 | PGM.3 48.77,47.14 48.36,46.74 48.36,34.54 | v13.82,52.83 14.63,52.02 24.79,52.02 26.06,50.75 GPS.9 26.06,48.72 28.45,46.33 33.73,46.33 35.76,44.3 35.76,40.52 37.45,38.83 39.2,38.83 ACCELEROMETER.GND 43.69,38.81 43.89,38.61 | 61.47,74.88 v61.47,74.45 61.47,76.3 61.37,76.4 | 52.83,76.4 52.63,76.2 | 56.31,75 v56.31,74.25 56.31,76.22 56.49,76.4 | 58.93,74.78 v58.93,74.37 58.93,76.4 | v52.99,33.1 53.02,33.1 53.02,34.36 52.83,34.54 | 58.52,34.54 v58.52,32.92 | v61.08,32.8 61.08,34.42 60.96,34.54 | 51.21,34.54 v51.21,32.92 | 94.69,37.39 v92.25,37.39 | v48.85,74.43 48.85,76.32 48.77,76.4 | v51.37,74.37 51.37,76.16 51.61,76.4 | v53.89,74.35 53.89,76.24 54.05,76.4 | U$15.P$1 36.54,75.15 37.8,76.4 45.52,76.4 | 76.81,76.4 77.22,76 | v20.32,2.85 11.61,2.85 J1.GND | v98.35,52.43 98.35,51.21 97.13,49.99 95.1,49.99 94.69,49.58
  Bottom 1.422: v55.35,10.3 53.1,10.3 52.43,10.97 52.43,14.63 52.28,14.77
  Bottom 1.524: 97.33,28.85 3.3VOLTOUT.2 | 64.62,17.48 62.59,17.48 60.55,17.48 | 95.81,30.38 97.33,28.85 | 95.81,30.38 94.69,31.5 94.69,37.39 94.69,49.58 94.69,52.43 91.44,55.68 91.44,58.93 91.44,62.99 | 64.62,17.48 65.02,17.88 65.02,21.59 65.02,27.23 65.02,33.33 63.8,34.54 61.77,34.54 60.96,34.54 58.52,34.54 52.83,34.54 51.21,34.54 48.36,34.54 46.74,34.54 43.89,37.39 43.89,38.61 43.89,44.7 | 43.89,44.7 43.89,56.9 | 45.52,76.4 48.77,76.4 51.61,76.4 52.83,76.4 54.05,76.4 56.49,76.4 58.93,76.4 61.37,76.4 76.81,76.4 78.44,76.4 86.16,76.4 91.44,71.12 91.44,62.99 | 94.28,28.85 94.08,28.65 92.66,27.23 92.66,26.82 92.66,21.54 89,17.88 89,14.63 | 94.28,28.85 95.81,30.38 | 97.33,28.85 5VOLTOUT.2 | v89,29.67 93.47,29.67 94.28,28.85 | 89,14.63 89,12.6 v92.25,12.6 | 64.62,17.48 65.43,17.48 | 65.43,17.48 73.56,17.48 76.4,14.63 89,14.63 | D1.A 65.63,17.27 65.43,17.48 | 55.29,10.24 v55.35,10.3 55.27,10.22 v55.27,6.5 | v50.6,16.46 52.28,14.77 | 86.56,63.4 91.03,63.4 91.44,62.99 | J1.GND 9.62,4.47 6.5,4.47 5.69,5.28 v5.69,18.54 5.69,21.08 LM7809.GND | U$16.8 U$16.2 37.34,45.97 38.61,44.7 43.89,44.7 | 59.02,18.61 60.15,17.48 60.55,17.48 | 52.43,14.63 57.71,14.63 60.55,17.48
  pour Bottom (isolate 0.305): 1.63,72.34 6.91,79.25 90.22,79.25 97.54,71.93 97.94,8.13 91.03,1.63 7.32,1.63 1.63,8.13
N$1
  Top 0.406: R26.1 R1.1 C1.1
N$2
  Top 0.229: U$1.P$64 78.65,50.2 78.84,50.39 78.84,52.43 80.06,53.65 81.75,53.65
  Top 0.254: R10.2 82.67,48.82 81.75,49.74 | 81.75,55.28 OSC.P$2
  Top 0.406: 81.75,49.74 81.75,53.65 81.75,55.28 | 85.24,58.62 C7.1 86.08,58.93 86.16,58.93 85.75,59.33 | OSC.P$2 82.09,56.15 82.09,58.93 82.91,59.74 84.12,59.74 84.53,59.33 85.75,59.33 | 85.75,59.33 85.81,59.4 85.81,59.88 86.08,60.15 95.5,60.15 97.13,58.52 97.13,56.74 JP2.1
N$3  (via drill 0.5)
  Top 0.229: v68.74,41.37 68.33,41.79 U$1.P$33 U$1.P$32 | THERMOMETER.3 73.15,31.06 73.15,34.54 70.86,36.84 v69.05,36.84 | U$15.P$3 41.24,68.08 47.55,61.77 47.55,56.9 47.95,56.49 v48.77,56.49
  Bottom 0.229: v48.77,56.49 50.39,56.49 55.27,51.61 55.27,49.58 56.49,48.36 67.46,48.36 67.87,47.95 67.87,42.24 v68.74,41.37 69.05,41.07 v69.05,36.84
  Bottom 0.406: R13.1 77.6,24 73.15,28.45 73.15,30.96 THERMOMETER.3
N$4  (via drill 0.6)
  Top 0.229: v59.33,45.52 61.81,45.52 61.91,45.41 63.32,45.41 U$1.P$24
  Bottom 0.406: PGM.1 50.6,42.06 52.02,43.48 52.02,45.11 52.43,45.52 v59.33,45.52
N$5  (via drill 0.5, 0.6)
  Top 0.229: v60.55,44.7 61.3,44.7 61.59,44.99 63.31,44.99 U$1.P$25
  Top 0.406: PGM.2 53.34,44.6 v54.05,43.89
  Bottom 0.406: v54.05,43.89 59.74,43.89 v60.55,44.7
N$6
  Top 1.422: 49.99,11.99 49.99,12.19 52.83,15.04 56.08,15.04 57.25,13.87 IC1.1
  Top 1.524: BATT.OUT 41.47,15.83 42.27,15.04 42.27,7.7 43.26,6.71 46.24,6.71 C14.+ 48.53,6.67 49.99,8.13 49.99,11.99
  Bottom 1.524: DC.OUT 34.56,13.43 36.98,15.85 39.25,15.85 BATT.OUT
N$7  (via drill 0.6)
  Top 0.406: R2.1 83.09,51.79 85.75,54.46 85.75,55.96 C8.2 84.47,57.28 v84.35,57.28 | OSC.P$1 82.55,61.32 82.91,60.96 v84.12,60.96
  Bottom 0.406: v84.12,60.96 84.12,57.51 v84.35,57.28
N$8  (via drill 0.6)
  Top 0.229: 76.4,40.64 75.13,41.92 U$1.P$50 75.13,44.76 74.37,45.52 v74.37,47.14
  Top 0.254: 76.4,40.64 80.47,40.64 80.87,40.23 80.87,32.11 81.28,31.7 82.35,31.7 JP1.5
  Bottom 0.254: v74.37,47.14 74.37,52.83 73.97,53.24
  Bottom 0.406: GPS.15 18.44,65.68 21.13,62.99 44.7,62.99 47.14,60.55 66.65,60.55 73.97,53.24
N$9
  Top 0.406: LED7.C 51.39,66.37 R31.2
N$10  (via drill 0.5)
  Top 0.229: 55.69,20.57 U$17.VDD 55.69,20.57 R14.1 51.03,20.45 v49.28,20.45 | C30.1 52.32,27.69 v49.66,25.02
  Bottom 0.229: v49.66,25.02 49.66,20.83 v49.28,20.45
N$11
  Top 0.406: ACCELEROMETER.GSEL 43.48,23.57 44.7,24.79 44.7,28.83 R15.1
  Bottom 0.406: ACCELEROMETER.GSEL 36.98,23.57 36.58,23.98 36.58,27.64 37.39,28.45 39.01,28.45 ACCELEROMETER.SLP
N$12  (via drill 0.5)
  Top 0.229: U$17.VSS 56.85,21.89 57.15,21.59 57.15,18.67 56.77,18.29 53.37,18.29 v52.96,18.69
  Bottom 1.524: U$6.P$2 47.55,1.9 47.55,6.1 42.67,10.97 42.67,16.26 45.11,18.69 v52.96,18.69 53.34,18.69 56.19,18.69 R18.1
N$13
  Top 0.406: R9.2 8.15,52.05 GPS.3
N$14
  Top 0.229: 65.57,62.85 66.65,61.77 67.61,61.77 69.74,59.64 71.63,59.64 71.93,59.33 U$1.P$84
  Top 0.254: JP3.9 65.06,66.04 65.57,65.53 65.57,62.85
N$15
  Top 0.229: U$1.P$100 65.53,58.83 65.02,59.33 51.21,59.33 48.77,61.77 48.77,63.32 LED8.A
N$16
  Top 0.254: R8.1 28.46,49.52 GPS.10
N$17
  Top 0.254: R7.1 25.31,53.71 GPS.7
N$18
  Top 0.254: R6.1 21.96,52.89 GPS.6
N$19
  Top 0.254: R5.1 18.64,52.12 GPS.5
N$20
  Top 1.524: DC.IN 32.46,18.75 24.79,26.42 4.88,26.42 2.95,24.49 2.95,21.95 | 2.85,21.18 LM7809.IN 2.95,21.95 | 2.95,21.95 2.85,21.84 2.85,13.82 6.01,10.65 J1.PWR 10.1,10.94 13.23,10.94 13.46,11.18 13.46,13.19 C5.1
N$21
  Top 0.229: 51.64,63.37 LED7.A 51.21,63.22 51.21,61.77 53.24,59.74 65.43,59.74 65.93,59.24 U$1.P$99
N$22
  Top 0.229: U$1.P$98 66.33,59.66 65.84,60.15 55.27,60.15 54.05,61.37 54.05,63.22 LED6.A
N$23
  Top 0.229: U$1.P$97 66.73,59.9 66.08,60.55 57.71,60.55 56.49,61.77 56.49,63.32 LED5.A
  Top 0.254: LED5.A 56.44,63.04 | U$1.P$97
N$24
  Top 0.229: U$1.P$96 67.13,60.48 66.65,60.96 59.74,60.96 58.93,61.77 58.93,63.32 LED4.A
N$25
  Top 0.229: U$2.IN2 U$2.IN1 | U$2.IN2 27.2,6.98 27.51,6.68 27.51,6.04 27.13,5.66 26.18,5.66 U$2.ISNS | 21.67,10.27 22.96,8.98 24.34,8.98 24.79,8.53 24.79,7.46 25.26,6.99 U$2.IN2
  Top 0.406: 21.67,10.27 R22.2
N$26  (via drill 0.6)
  Top 0.229: U$2.APG/THERM 26.17,4.39 27.64,4.39 28.14,4.9 28.14,7.95 27.13,8.97 25.35,8.97 25.35,11.48 25.98,12.52 27,12.52 | R23.1 23.27,7.82 v23.61,7.48 | v28.65,12.25 28.65,12.8 28.45,13.01 27.11,13.01
  Top 0.406: 27,12.52 R24.2 27.11,13.01
  Bottom 0.406: v28.65,12.25 28.67,12.23 28.67,10.69 25.46,7.48 v23.61,7.48
N$27  (via drill 0.5, 0.6)
  Top 0.229: v73.01,37.37 73.01,38.34 72.75,38.61 72.75,42.79 U$1.P$44
  Top 0.406: v62.99,27.64 v68.28,27.64
  Bottom 0.406: v68.28,27.64 70.71,27.64 71.53,28.45 71.53,36.58 72.34,37.39 72.99,37.39 v73.01,37.37 | ACCELEROMETER.0GD 55.37,26.11 56.9,27.64 v62.99,27.64
N$28
  Top 0.229: C17.1 33.66,8.36 32.96,7.66 31.79,7.66 U$2.OUT1 U$2.OUT2 U$2.VSENSE
  Top 0.406: 38.02,18.51 45.11,18.51 R19.2
  Top 1.524: 38.02,18.51 36.98,17.48 36.98,15.44 35.36,13.82 35.36,9.8 35.41,9.75 | 35.41,9.75 C17.1 35.44,8.39 38.32,8.39 38.59,8.13 38.61,8.13 41.71,5.03 41.71,4.99 42.59,4.11 42.59,1.84 U$6.P$1 | 35.41,9.75 35.41,10.62 36.17,11.38 37.35,11.38 BATT.IN
N$29
  Top 0.229: U$1.P$95 67.54,56.82 67.54,60.86 67.46,60.94 67.46,60.96 67.06,61.37 61.83,61.37 61.53,61.67 LED3.A
  Top 0.254: LED3.A 61.52,63.25
N$30
  Top 0.229: C16.1 27.84,10.36 28.85,9.35 28.85,4.11 29.87,3.09 U$2.CR
N$31
  Top 0.229: R27.2 LED2.A
N$32
  Top 0.229: R25.2 LED1.A
N$33
  Top 0.203: U$1.P$76 75.13,61.72
  Top 0.229: 75.13,61.72 76.4,62.99 76.4,64.11 JP3.1
N$34
  Top 0.229: U$2.STAT1 30.16,4.38 29.67,4.88 29.67,14.63 28.85,15.44 LED1.C
N$35
  Top 0.229: LED2.C 29.97,17.98 30.48,17.48 30.48,5.41 30.82,5.06 31.73,5.06 U$2.STAT2
N$36
  Top 0.406: R32.1 82.11,9.37 84.94,12.19 | R33.1 82.24,11.52 83.92,13.21
  Top 1.422: IC1.4 53.72,8.61 52.43,7.32
  Top 1.524: C18.+ 92.25,8.14 92.25,4.88 91.44,4.06 83.31,4.06 83.11,3.86 80.89,3.86 | C18.+ 96.39,8.2 97.54,9.35 97.54,20.69 5VOLTOUT.1 97.3,20.93 VREG.3 | U$5.P$4 82.52,14.61 83.92,13.21 84.94,12.19 89,8.13 92.24,8.13 C18.+ | 52.43,7.32 52.43,6.1 54.05,4.47 58.58,4.47 61.16,1.89 U$7.P$1 71.23,2.29 73.33,4.39 80.37,4.39 80.78,3.97 80.89,3.86 | U$7.P$3 80.92,3.83 80.89,3.86
N$37  (via drill 0.6)
  Top 0.229: U$1.P$11 67.67,50.6 v69.09,52.02
  Bottom 0.229: v69.09,52.02 69.09,53.24 68.68,53.65 66.24,53.65 63.8,56.08 53.14,56.08 UART3.2
N$38  (via drill 0.51)
  Top 0.229: C15.1 R25.1 | R25.1 R27.1 C12.1 | R25.1 18.74,15.57 | R22.1 R23.2 18.87,6.68 19.25,6.3 24.84,6.3 | 19,10.49 19,12.9 | 24.84,6.3 26.12,6.3 U$2.VCC | U$2.VSEL U$2.EN 24.99,3.73 24.71,4.01 24.71,6.17 24.84,6.3 | v14.22,19.51 14.9,18.83 C99.+ 18.66,18.19
  Top 0.406: 18.67,17.78 R27.1 18.66,18.19 | 19,12.9 C15.1 | R22.1 19,10.49
  Bottom 0.406: v14.22,19.51 9.8,19.51 LM7809.OUT
N$39
  Top 0.203: 74.74,61.77 74.74,56.81 U$1.P$77
  Top 0.229: JP3.2 74.47,62.04 74.74,61.77
N$40
  Top 0.203: U$1.P$78 74.33,61.41
  Top 0.229: 74.33,61.41 73.23,62.5 73.23,64.74
  Top 0.254: 73.23,64.74 JP3.3
N$41
  Top 0.203: 73.94,61.02 73.94,56.82 U$1.P$79
  Top 0.229: JP3.4 71.93,63.03 73.94,61.02
N$42
  Bottom 0.406: U$15.P$2 38.89,71.65 40.23,70.31 72.34,70.31 76.28,66.36 76.28,35.09 75.74,34.55 THERMOMETER.2
N$43
  Top 0.229: U$1.P$81 73.13,60.5 72.48,61.14 70.94,61.14 69.49,62.59
  Top 0.254: 69.49,62.59 69.49,63.4 JP3.6
N$44
  Top 0.229: U$1.P$83 72.33,59.83 72.01,60.15 69.9,60.15 67.06,62.99
  Top 0.254: 67.06,62.99 67.06,63.3 JP3.8
N$45  (via drill 0.5 pad 0.25, 0.6 pad 0.25)
  Top 0.229: 71.53,41.45 U$1.P$41
  Top 0.254: v71.93,41.05 71.53,41.45
  Top 0.406: v63.62,28.57 67.99,28.57 68.28,28.85 v68.28,29.69
  Bottom 0.406: v71.93,41.05 71.93,39.42 70.04,37.53 70.04,35.84 67.06,32.86 67.06,31.7 68.28,30.48 v68.28,29.69 | ACCELEROMETER.XOUT 49.28,31.19 51.21,29.26 53.24,29.26 54.46,30.48 61.71,30.48 v63.62,28.57
N$46  (via drill 0.5 pad 0.25, 0.5 pad 0.41, 0.6 pad 0.41)
  Top 0.229: U$1.P$42 71.93,44.02 70.43,45.52 v65.84,45.52
  Top 0.406: v57.06,32.94 57.06,35.6 v57.42,35.97
  Bottom 0.406: ACCELEROMETER.YOUT 45.27,33.73 46.11,32.9 49.2,32.9 50.94,31.15 55.27,31.15 v57.06,32.94 | v65.84,45.52 57.4,37.08 57.42,37.06 v57.42,35.97
N$47  (via drill 0.5, 0.6 pad 0.25)
  Top 0.229: U$1.P$43 72.33,44.33 70.33,46.33 70.31,46.33
  Top 0.254: v66.24,47.14 68.68,47.14 69.49,46.33 70.31,46.33
  Top 0.406: ACCELEROMETER.ZOUT 47.45,36.27 47.55,36.17 49.2,36.17 v49.38,35.99
  Bottom 0.406: v49.38,35.99 55.09,35.99 v66.24,47.14
N$48
  Top 0.203: 69.9,41.05 69.9,42.78 U$1.P$37 69.9,42.83 69.9,44.7
  Top 0.229: 64.31,43.04 65.43,44.16 | 69.9,44.7 69.66,44.95 66.55,44.95 65.76,44.16 65.45,44.16
  Top 0.254: C10.1 71.3,40.46 71.12,40.64 70.31,40.64 69.9,41.05 | R4.1 63.75,43.03 63.76,43.04 64.31,43.04 | 65.43,44.16 65.45,44.16
N$49
  Top 0.229: U$1.P$80 73.53,60.73 72.62,61.63 71.26,61.63 70.71,62.18 70.71,62.26 70.67,62.3 70.67,64.68 70.71,64.72
  Top 0.254: 70.71,64.72 JP3.5
N$50
  Top 0.229: 68.13,62.71 70.1,60.74 72.18,60.74 72.72,60.19 U$1.P$82
  Top 0.254: JP3.7 66.85,66.02 68.13,64.74 68.13,62.71 | U$1.P$82
N$51
  Top 0.229: 61.37,39.83 62.51,39.83 C11.1 64.23,40.34 64.31,40.42 64.31,41.37 64.56,41.62 66.93,41.62 67.12,41.8 67.12,42.79 U$1.P$30
  Top 0.254: R4.2 59.97,41.23 61.37,39.83
N$52  (via drill 0.6)
  Top 0.229: U$1.P$12 69.31,50.2 v70.31,51.21
  Bottom 0.229: v70.31,51.21 70.31,53.65 69.09,54.86 67.87,54.86 65.02,57.71 UART3.1
N$53
  Top 0.406: R21.2 61.52,69.86 LED3.C
N$54
  Top 0.406: R28.2 58.98,69.72 LED4.C
N$55
  Top 0.406: R29.2 56.44,69.72 LED5.C
N$56
  Top 0.406: R30.2 LED6.C
N$57
  Top 0.229: U$1.P$63 79.24,49.8 R10.1 | JP2.2 94.69,56.54 94.69,54.86 94.28,54.46 90.63,54.46 87.78,51.61 84.94,51.61 84.53,51.21 84.53,47.55 84.12,47.14 82.09,47.14 81.69,47.55 81.69,48.36 81.25,48.8 80.47,48.8
  Top 0.254: R10.1 80.1,49.21 80.29,49.4
  Top 0.406: 80.29,49.4 R2.2 | R10.1 80.47,48.8
N$58
  Top 0.406: R20.2 48.82,69.71 LED8.C
N$59  (via drill 0.5)
  Top 0.229: U$1.P$94 67.93,57.77 68.28,58.12 69.9,58.12 v70.31,58.52 | v71.53,69.09 71.53,73.33 R11.2
  Bottom 0.229: v71.53,69.09 70.67,68.23 70.67,62.59 70.31,62.22 v70.31,58.52
N$60
  Top 0.229: U$1.P$13 62.34,49.8 62,50.15 62,53.42
  Top 0.406: PGM.5 51.86,52.22 52.01,52.38 R26.2 53.65,52.4 53.65,53.65 54.05,54.05 58.52,54.05 58.83,53.75 61.67,53.75 62,53.42
N$61  (via drill 0.5, 0.6)
  Top 0.229: v78.84,46.74 78.68,46.9 78.68,47.41 78.28,47.8 U$1.P$58 77.32,47.81 | v84.53,26.42 84.53,37.13 JP1.2
  Top 0.406: 66.24,30.48 65.17,29.41 U$4.1 60.91,29.23 R17.2 | 66.24,30.48 v68.28,32.51 | v67.87,23.98 68.05,23.8 68.05,20.54 71.12,17.48 72.72,17.48 73.4,16.8 R33.2 73.15,14.3 | v66.87,29.63 66.87,29.85 66.24,30.48
  Bottom 0.229: 78.84,40.31 v78.84,46.74 | v68.28,32.51 70.71,34.95 70.71,36.58 72.75,38.61 73.56,38.61 73.97,38.2 73.97,32.98 74.49,32.45 74.49,29.95 79.65,24.79 82.91,24.79 v84.53,26.42
  Bottom 0.254: 78.84,40.31 79.82,39.34 82.33,39.34 JP1.2
  Bottom 0.406: v67.87,23.98 67.87,24.83 66.59,26.11 66.59,29.34 v66.87,29.63
N$62
  Top 0.229: R17.1 60.91,23.8 61.09,23.62 62.74,23.62 63.5,22.86 63.5,21.46 63.25,21.21 59.9,21.21 U$17.SCL
N$63
  Top 0.406: MAX3232.T2OUT 92.78,45.81 93.07,45.52 96.72,45.52 U$9.RX
N$64
  Top 0.229: R12.2 49.53,28.57 48.01,28.57 47.52,28.09 47.52,23.73 R19.1 48.92,23.47 49.28,23.11 49.28,22.35 49.66,21.97 53.34,21.97 53.98,21.34 55.61,21.34 U$17.VIN
N$65
  Top 0.229: R11.1 79.53,73.56 T1.2
N$66  (via drill 0.5)
  Top 0.406: v86.97,13.01 86.97,17.07 85.34,18.69 85.34,22.78 87.94,25.38 92.03,25.38 93.07,26.42 93.07,27.96 v89.9,31.13 | T1.1 84.53,71.53 87.78,68.28 v87.78,61.77
  Bottom 0.406: 83.01,4.88 83.01,4.47 | 83.01,4.88 83.01,6.2 84.12,7.32 84.12,10.16 v86.97,13.01 | v87.78,61.77 87.78,56.08 90.22,53.65 90.22,39.01 88.19,36.98 88.19,32.92 89.9,31.21 v89.9,31.13 | 83.41,4.47 83.01,4.88
  Bottom 1.524: U$7.P$2 75.84,3.5 76.81,4.47 83.41,4.47 U$7.P$4
N$67
  Top 0.254: R3.1 15.39,51.41 GPS.4
N$68
  Top 1.524: VREG.2 89.05,22.81 90.22,23.98 93.07,23.98 94.69,25.6 94.69,30.48 94,31.17 | 94,31.17 93.47,31.7 91.88,31.7 RESET.IN | 3.3VOLTOUT.1 95.11,32.28 94,31.17
N$69  (via drill 0.6)
  Top 0.229: U$1.P$53 83.74,45.8 84.39,46.45
  Top 0.254: 84.39,46.45 MAX3232.R2OUT
  Top 0.406: v86.16,48.36 86.16,46.62 MAX3232.R2OUT
  Bottom 0.406: JP1.3 83.46,36.73 84.53,37.8 84.53,46.74 v86.16,48.36
N$70
  Top 0.229: U$17.SDA 58.91,20.59 58.42,21.08 58.42,22.73 58.17,22.99 R16.2
N$73
  Top 0.229: 75.59,60.55 75.59,55.27 75.18,54.86 71.93,54.86 71.53,55.27 U$1.P$85
  Top 0.254: C13.A 77.09,62.05 75.59,60.55
N$92  (via drill 0.6)
  Top 0.229: v72.75,47.95 72.75,45.96 74.74,43.97 74.74,42.81 U$1.P$49 74.73,40.98 75.71,39.99 78.8,39.99 80.08,38.71 80.08,29.81 80.79,29.1 82.39,29.1 JP1.6
  Bottom 0.406: GPS.17 13.36,65.08 16.26,62.18 44.3,62.18 46.74,59.74 65.84,59.74 72.75,52.83 v72.75,47.95
N$96  (via drill 0.9)
  Top 1.422: IC1.2 54.63,12.01 v54.05,12.6
  Bottom 1.422: v54.05,12.6 60.96,12.6
  Bottom 1.524: D1.C 65.17,6.6 | D1.C 72.91,6.66 73.56,7.32 77.43,7.32 U$5.P$1 | 60.96,12.6 61.77,11.79 61.77,7.56 62.63,6.71 65.59,6.71 D1.C
N$97  (via drill 0.5, 0.6)
  Top 0.229: U$1.P$59 78.59,48.2 v80.06,46.74 | 59.15,19.1 59.15,19.33 57.78,20.7 57.78,22.35 54.99,25.15 54.99,26.54 55.88,27.43 58.14,27.43 R16.1
  Top 0.406: R16.1 58.27,27.51 U$11.1 59.51,29.43 60.55,30.48 63.4,30.48 v67.06,34.14 | v77.62,35.76 73.15,35.76 71.12,37.8 68.28,37.8 68.19,37.71 v68.13,37.71 | R32.2 73.42,7.74 73.23,7.92 72.22,7.92 71.95,8.19 71.95,15.42 68.28,19.1 59.15,19.1
  Bottom 0.229: 80.06,44.15 v80.06,46.74 | v77.62,35.76 79.25,37.39 80.87,37.39 81.28,37.8 81.28,37.82 81.44,38 83.5,38 83.72,38.2 83.72,40.49 83.16,41.05
  Bottom 0.254: 80.06,44.15 JP1.1 83.16,41.05
  Bottom 0.406: v67.06,34.14 67.06,37.31 67.48,37.73 68.11,37.73 v68.13,37.71
N$116  (via drill 0.6)
  Top 0.229: U$1.P$52 84.09,45.4 84.49,45.8 MAX3232.T2IN | v89,40.64 89,43.48 87.38,45.11 87.38,45.48 87.07,45.78 86.02,45.78 MAX3232.T2IN
  Top 0.254: MAX3232.T2IN
  Bottom 0.406: JP1.4 82.55,34.19 v89,40.64
N$117
  Top 0.229: MAX3232.C1+ 91.59,41.7 93.47,39.83 93.47,35.76 93.88,35.36 95,35.36 C21.PLUS
N$118
  Top 0.229: C21.MINUS 95.2,42.57 94.69,43.08 91.72,43.08 MAX3232.C1-
N$119
  Top 0.229: MAX3232.C2+ 89.73,43.86 88.53,45.05 88.53,50.05 88.19,50.39 86.26,50.39
  Top 0.406: 85.85,50.39 C22.PLUS 86.26,50.39
N$120
  Top 0.229: MAX3232.C2- 91.59,44.5 90.08,44.5 89.41,45.17 89.41,48.36 90.34,49.29 90.34,50.04 C22.MINUS
N$121
  Top 0.229: MAX3232.V- 90.58,45.16 90.22,45.52 90.22,47.95 91.03,48.77 91.85,48.77 92.66,49.58 92.66,51.61 92.25,52.02 92.25,52.53 C19.PLUS
N$122
  Top 0.229: C20.MINUS 91.2,40.06 89.81,41.45 89.81,41.96 90.32,42.47 91.51,42.47 MAX3232.V+
N$123
  Top 0.406: MAX3232.R2IN 96.75,46.46 U$9.TX
VDD  (via drill 0.5, 0.6)  (2 unrouted)
  Top 0.203: 73.56,40.64 73.56,42.77 U$1.P$46 73.53,44.53
  Top 0.229: 77.49,56.36 75.59,54.46 71.53,54.46 | 71.53,54.46 71.12,54.86 | 71.12,54.86 U$1.P$86 | 61.34,47.11 61.77,47.55 61.77,48.28 62.1,48.6 U$1.P$16 | 61.77,54.86 62.43,54.2 U$1.P$2 63.34,54.21 65.45,54.21 66.1,54.86 71.12,54.86 | MAX3232.VCC 86,41.37 85.14,40.52 85.14,40.03 84.94,39.83 84.94,38.2 89,34.14 | 71.53,54.46 71.53,49.99 71.93,49.58 | 55.07,48.13 55.07,48.97 54.86,49.17 54.02,49.17 R1.2 | 73.53,44.53 71.73,46.33 71.73,49.38 71.93,49.58 | 71.93,49.58 72.16,49.36 75.83,49.36 75.88,49.4 U$1.P$62 | R14.2 52.58,23.37 v53.09,23.88
  Top 0.254: 77.49,56.36 C4.1 | 73.56,40.64 74.78,39.42 77.22,39.42 77.6,39.04 C9.1 77.62,38.08 | 61.77,54.86 60.78,54.86 C3.1 | C6.1 76.5,43.18 76,42.67 76,42.27 76.81,41.45 80.75,41.45 81.69,40.52 85.14,40.52
  Top 0.406: 60.15,47.14 59.33,47.14 58.12,45.92 58.12,44.3 | R1.2 52.33,49.53 52.2,49.66 50.69,49.66 PGM.4 | 55.07,48.13 55.07,45.15 55.92,44.3 58.12,44.3 | R8.2 28.45,58.52 28.45,60.55 | 24.79,58.52 R7.2 25.6,58.81 25.6,60.55 | 21.96,58.51 R6.2 21.95,58.51 21.95,60.55 | 18.64,58.57 R5.2 18.69,58.55 18.69,60.55 | R3.2 15.39,58.57 15.44,58.62 15.44,60.55 | 77.62,38.08 77.62,37.39 | 58.12,37.39 58.12,44.3 | 72.75,19.51 v72.75,21.95 | 69.9,25.6 v62.99,25.6 | 45.52,41.45 45.41,41.35 ACCELEROMETER.VCC 39.2,43.08 | 39.2,43.08 45.52,43.08 | 45.52,55.27 60.55,55.27 | 45.52,49.58 45.62,49.68 50.76,49.68 50.78,49.7 | v79.25,35.76 79.25,37.8 78.84,38.2 77.7,38.2 C9.1 | 39.2,43.08 25.2,43.08 23.52,44.76 GPS.8 | R15.2 46.71,31.68 49.99,34.95 51.61,34.95 52.43,35.76 52.43,37.39 | v85.75,32.92 86.16,32.92 87.85,31.22 | C2.1 61.34,47.11
  Top 1.524: 91.03,34.95 89.81,34.95 89,34.14 88.74,33.87 88.74,32.11 87.85,31.22 86.16,29.52 86.16,25.6 84.53,23.98 81.28,23.98 80.06,22.76 80.06,19.51 78.03,17.48 76.81,17.48 74.78,19.51 72.75,19.51 71.12,19.51 69.9,20.73 69.9,25.6 69.9,33.73 66.24,37.39 58.12,37.39 52.43,37.39 49.17,37.39 45.52,41.05 45.52,41.45 45.52,43.08 45.52,49.58 45.52,55.27 45.52,56.49 43.89,58.12 40.23,58.12 | 8.53,59.33 9.75,60.55 15.44,60.55 18.69,60.55 21.95,60.55 25.6,60.55 28.45,60.55 32.92,60.55 35.36,58.12 40.23,58.12 | U$16.1 U$16.3 U$16.5 U$16.7 39.88,57.76 40.23,58.12
  Bottom 0.229: v79.25,35.76 79.25,33.33 80.06,32.51 80.06,28.45 80.87,27.64 83.09,27.64 84.67,29.22 84.67,31.84 v85.75,32.92
  Bottom 0.406: R13.2 73.61,22.81 v72.75,21.95 | v53.09,23.88 61.27,23.88 v62.99,25.6

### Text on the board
tPlace: The Incredible HUD | HUD Mk III | TEAM 03 | ECE 477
